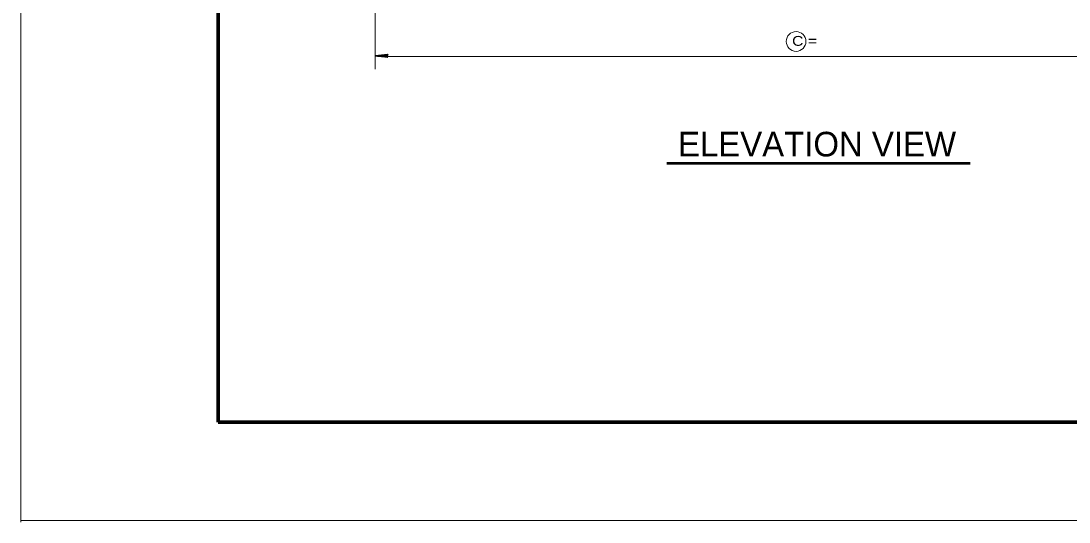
# Model space of a CAD drawing. Extents: x 3.64 to 6.84, y -0.8 to 1.19.
# Drawn here: x 3.645 to 4.532, y -0.796 to -0.372 of the extents above; entities that cross this region are included whole.
import ezdxf

# ---------------------------------------------------------------- set-up
doc = ezdxf.new("R2010")
doc.units = 0
doc.header["$LTSCALE"] = 0.0033
doc.layers.add('1', color=7, linetype='Continuous', lineweight=40)

msp = doc.modelspace()

# ---------------------------------------------------------------- linework, layer by layer
at = {"layer": '1', "lineweight": 13}
for p, q in [((3.644833, -0.795833), (3.644833, 1.192417)), ((3.944417, -0.152333), (3.944417, -0.41275)), ((3.9465, -0.401917), (4.3295, -0.401917)), ((4.327667, -0.401917), (4.693083, -0.401917)), ((6.841583, -0.794667), (3.644833, -0.794667))]:
    msp.add_line(p, q, dxfattribs=at)
at = {"layer": '1', "lineweight": 35}
for p, q in [((3.955167, -0.401417), (3.944583, -0.401417)), ((3.954917, -0.40225), (3.947083, -0.40125)), ((3.954917, -0.40225), (3.947083, -0.401417)), ((3.954917, -0.402417), (3.947083, -0.4015)), ((3.954917, -0.402417), (3.947083, -0.4015)), ((3.954917, -0.402333), (3.947083, -0.4015)), ((3.954917, -0.400333), (3.947583, -0.401167)), ((3.954917, -0.4005), (3.947583, -0.40125)), ((3.954917, -0.400583), (3.947583, -0.401417)), ((3.955, -0.40075), (3.947667, -0.4015))]:
    msp.add_line(p, q, dxfattribs=at)
at = {"layer": '1', "lineweight": 53}
msp.add_line((4.191333, -0.49225), (4.447833, -0.49225), dxfattribs=at)
at = {"layer": '1', "lineweight": 70}
msp.add_line((3.811583, -0.711333), (6.75825, -0.711333), dxfattribs=at)
msp.add_lwpolyline([(6.75825, -0.711333), (6.75825, 1.10875), (3.811583, 1.10875), (3.811583, -0.711333)], dxfattribs=at)
at = {"layer": '1'}
msp.add_lwpolyline([(3.811583, -0.711333), (6.17325, -0.711333), (6.17325, -0.38625), (6.75825, -0.38625)], dxfattribs=at)
at = {"layer": '1', "lineweight": 35}
for points in [[(3.955167, -0.4025), (3.944583, -0.401417), (3.955167, -0.40025), (3.954583, -0.401417)], [(3.954417, -0.4015), (3.94975, -0.401583), (3.94975, -0.4015), (3.950667, -0.4015), (3.954417, -0.401583), (3.951417, -0.401667), (3.954583, -0.40175), (3.952333, -0.401833), (3.954583, -0.401917), (3.951083, -0.401667), (3.946417, -0.4015), (3.947333, -0.40125), (3.946083, -0.40125), (3.954417, -0.40125), (3.952, -0.401083), (3.954583, -0.401083), (3.94925, -0.4015), (3.954583, -0.400833)]]:
    msp.add_lwpolyline(points, close=True, dxfattribs=at)
msp.add_lwpolyline([(3.954417, -0.4015), (3.954833, -0.40225), (3.954583, -0.402), (3.954417, -0.401667), (3.954167, -0.40175), (3.954333, -0.402083), (3.9545, -0.401333), (3.954667, -0.400833), (3.954917, -0.400417)], dxfattribs=at)
at = {"layer": '1', "lineweight": 13}
msp.add_circle((4.300667, -0.38925), 0.008333, dxfattribs=at)

# ---------------------------------------------------------------- texts
at = {"layer": '1', "width": 1.2}
msp.add_text('C =      ', height=0.008334, dxfattribs=at).set_placement((4.29725, -0.392917))
at = {"layer": '1'}
msp.add_text('ELEVATION VIEW', height=0.02083, dxfattribs=at).set_placement((4.20075, -0.4865))

doc.saveas('drawing.dxf')
